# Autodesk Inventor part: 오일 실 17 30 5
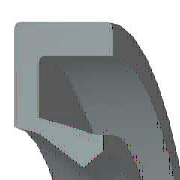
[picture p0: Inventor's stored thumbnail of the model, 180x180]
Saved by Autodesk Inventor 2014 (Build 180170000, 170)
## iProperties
Created: 2012-02
Part Number: 오일 실 17 30 5
Material: 고무
Description: 오일 실 - 스프링 장착, 비스프링, 고무 덮개 G
Document SubType Name: Modeling
Standard: JIS B 2402
Designer: mduedu
Standards Organization: JIS
Language: ko-KR
Size Designation: 17 30 5 A
Categories: <MemberInstance><Categories><Category DisplayName="샤프트 부품" InternalName="7f7aeb1f-a693-4053-b835-cee3144e0d98" Mnemonic="SHFT"><Category DisplayName="실링" Intern
Density: 0.93 g/cm^3
Appearance: 고무 - 검은색 - 버전 1.1
Mass: 1.22959 g
Surface Area: 18.6191 cm^2
Volume: 1.32214 cm^3
IsCustomPart: 1
Author: mduedu
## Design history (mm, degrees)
fillet "모깎기2" dims "d41" = 0.5
fillet "모깎기3" dims "d42" = 0.5
body "Solid1"
revolve "회전1" stored, may be unused: angle "d29" = 360 deg
fillet "모깎기1" dims "d34" = 0.25 (= 0.05 x b)
sketch "스케치2"
  geometry: L1 (9.58, -3.438)-(9.905, -5); L2 (9.147, -3.282)-(9.58, -3.438); L3 (8.5, -1.72)-(9.147, -3.282); L4 (9.682, -1.22)-(8.5, -1.72); L5 (10.811, -3.75)-(9.682, -1.22); L6 (12.111, -3.75)-(10.811, -3.75); L7 (13.556, -1.25)-(12.111, -3.75); L8 (13.556, 0)-(13.556, -1.25); L9 (15, 0)-(13.556, 0); L10 (15, -5)-(15, 0); L11 (9.905, -5)-(15, -5); L12 (0, -9.6)-(0, 1.6) reference; L13 (28, 0)-(14, 0) reference
  constraints: 22 end point, 3 horizontal, 2 vertical
  dimensions: "d2" = 5 distance of L10.start L9.start (= b); "d4" = 1.25 vertical distance of L5.start L1.end (= 0.25 x b); "d6" = 1.44444 distance of L9.start L8.start (= 0.111111 x dd - 0.111111 x Diam); "d8" = 1.25 distance of L8.start L7.start (= 0.25 x b); "d10" = 1.44444 horizontal distance of L7.start L6.start (= 0.111111 x dd - 0.111111 x Diam); "d12" = 1.21951 vertical distance of L9.start L4.start (= 0.243902 x b); "d14" = 1.18182 horizontal distance of L4.start L3.start (= 0.0909091 x dd - 0.0909091 x Diam); "d16" = 0.5 vertical distance of L4.start L3.start (= 0.1 x b); "d18" = 1.3 distance of L6.start L5.start (= 0.1 x dd - 0.1 x Diam); "d20" = 1.5625 vertical distance of L3.start L2.start (= 0.3125 x b); "d22" = 0.64677 horizontal distance of L3.start L2.start (= 0.0497512 x dd - 0.0497512 x Diam); "d24" = 0.325 horizontal distance of L1.start L1.end (= 0.025 x dd - 0.025 x Diam); "d26" = 1.5625 vertical distance of L1.start L1.end (= 0.3125 x b); "d28" = 0.43333 horizontal distance of L2.start L1.start (= 0.0333333 x dd - 0.0333333 x Diam); "d35" = 0 distance between parallel lines of L13 L9; "d36" = 15 distance between parallel lines of L12 L10 (= 0.5 x dd); "d37" = 8.5 distance from line of L12 L3.start (= 0.5 x Diam)
other parameters: "Diam" = 17 [user parameter; used in 8 equation terms], "b" = 5 [user parameter; used in 8 equation terms], "d1" = 8 (derived), "d3" = 2 (derived), "d5" = 2.22222 (derived), "d7" = 2 (derived), "d9" = 2.22222 (derived), "d11" = 1.95122 (derived), "d13" = 1.81818 (derived), "d15" = 0.8 (derived), "d17" = 2 (derived), "d19" = 2.5 (derived), "d21" = 0.99502 (derived), "d23" = 0.5 (derived), "d25" = 2.5 (derived), "d27" = 0.66667 (derived), "d38" = 0
